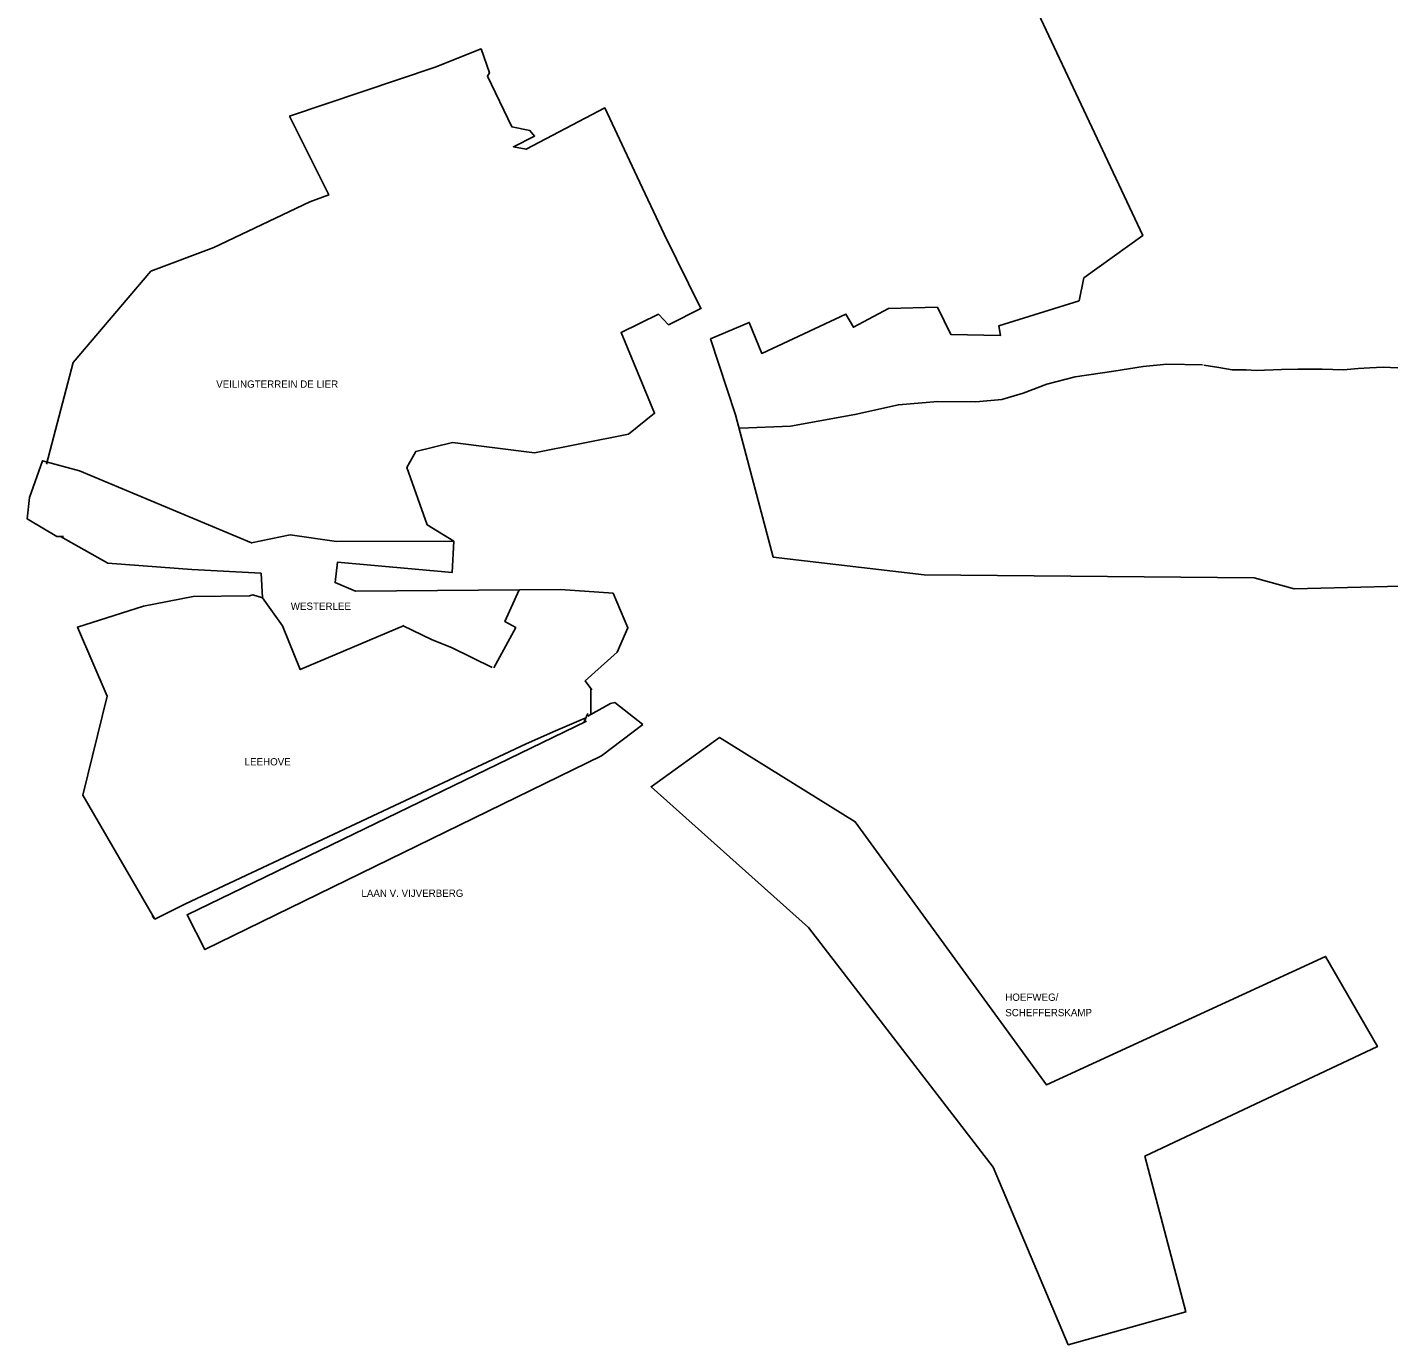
# Model space of a CAD drawing. Extents: x 69068 to 80855, y 440023 to 451362.
# Drawn here: x 74587 to 76267, y 442401 to 444027 of the extents above; entities that cross this region are included whole.
import ezdxf

# ---------------------------------------------------------------- set-up
doc = ezdxf.new("R2010")
doc.units = 0
doc.layers.add('Bemalingsgebiedsgrens', color=7, linetype='Continuous')
doc.layers.add('RIO_Leidingen', color=7, linetype='Continuous')

msp = doc.modelspace()

# ---------------------------------------------------------------- linework, layer by layer
at = {"layer": 'Bemalingsgebiedsgrens'}
for p, q in [((74876, 443353.2), (74790.3, 443357.4)), ((74877.6, 443322.6), (74876, 443353.2)), ((75086.2, 443271.4), (75051.2, 443287.9)), ((75111.7, 443261), (75086.2, 443271.4)), ((75161, 443236.7), (75111.7, 443261)), ((75282.5, 443179.3), (75282.6, 443211)), ((75274.4, 443169.4), (75279.1, 443179.8))]:
    msp.add_line(p, q, dxfattribs=at)
for points in [[(75831.3, 444051), (75963.9, 443769.8), (75890.9, 443717.4), (75885.1, 443689.3), (75785.9, 443658.2), (75788.1, 443646.3), (75726.8, 443647.6), (75710.2, 443681.2), (75650.1, 443679.5), (75606.7, 443656.5), (75597.4, 443672.7), (75493.5, 443624.2), (75478.2, 443662.5), (75430.5, 443642.1), (75461.2, 443548.4), (75507.7, 443372.6), (75694, 443350.9), (76100.9, 443347.5), (76150.3, 443333.9), (76298.4, 443337.3)], [(74611.3, 443487.5), (74644.1, 443612.9), (74740, 443725.6), (74817.6, 443755), (74935.9, 443811.2), (74959.4, 443819.8), (74911, 443917.1), (75090.7, 443977.6), (75147.3, 444000), (75157.6, 443970.5), (75155.1, 443966.5), (75185.1, 443903.9), (75207.5, 443899.2), (75213.3, 443892.5), (75187.2, 443879.3), (75202.8, 443876.1), (75300, 443927.1), (75336.5, 443849.3), (75373, 443771.6), (75418.4, 443679.5), (75416.6, 443679.3)], [(75419.1, 443680), (75378.7, 443659.7), (75366.2, 443672.6), (75320.1, 443650.1), (75361.4, 443550.5), (75329.1, 443524.4), (75213, 443501.6), (75112.2, 443514.2), (75066.7, 443503.3), (75055.7, 443483.3), (75080.6, 443412.8), (75113.6, 443392.5)], [(75466.9, 443531.9), (75529, 443534.4), (75608.5, 443548.7), (75662.2, 443560.9), (75710.7, 443564.8), (75757.5, 443564.3), (75789.6, 443567.3), (75816, 443575.1), (75845.3, 443586.3), (75880.4, 443595.2), (75927.8, 443602.2), (75964.3, 443608), (75993.5, 443610.8), (76037.5, 443610)], [(76038.9, 443609.7), (76057.3, 443606.9), (76074, 443604.1), (76091, 443603.8), (76103.6, 443603.3), (76134.8, 443604.4), (76155.1, 443604.7), (76184.9, 443604.9), (76211.1, 443604.1), (76229.5, 443605.8), (76243.7, 443606.6), (76260.4, 443607.2), (76278.5, 443606.3)], [(74591.2, 443417.7), (74587.4, 443420.1), (74590, 443446.6), (74606.1, 443491.8), (74651.8, 443479.2), (74864.1, 443390.4), (74911.8, 443400.5), (74968.9, 443392.1), (75113.6, 443392.5), (75111.5, 443353.7), (74970.2, 443366.8), (74967.2, 443341.5), (74992.5, 443330.7)], [(74632.1, 443398.3), (74623.8, 443398.5), (74589.3, 443418.9)], [(74790.3, 443357.4), (74686.9, 443365.4), (74628.3, 443398.4)], [(75276.7, 443174.6), (75276.7, 443174.6), (75239.2, 443158.3), (75203.1, 443142.3), (74782.6, 442944.8), (74744.8, 442926.2), (74744.8, 442926.2), (74741.8, 442929.2), (74744.8, 442926.2), (74744.8, 442926.2), (74656.1, 443079.3), (74685.8, 443201.1), (74649.4, 443286.6), (74731, 443312.2), (74791.9, 443324.1), (74861.5, 443325), (74865.7, 443326.5), (74877.6, 443322.6), (74902.2, 443287.9), (74924.1, 443234.1), (75052.5, 443288.6)], [(74992.5, 443330.7), (75245.4, 443332.9), (75310.1, 443328.3), (75328.5, 443285.4), (75315.3, 443255.4)], [(75194.3, 443332.3), (75176.8, 443293.3), (75190.1, 443285.9), (75162.9, 443236.4)], [(75315.3, 443255.4), (75275.8, 443220.2), (75283.8, 443209)], [(75306.8, 443192.2), (75278.9, 443176.7)], [(75347, 443166.5), (75312.5, 443193.4), (75306.8, 443192.4)], [(75277.2, 443170.6), (74784.5, 442931.5), (74806.5, 442888.5), (75295.9, 443127.5), (75347, 443166.5)]]:
    msp.add_lwpolyline(points, dxfattribs=at)
msp.add_lwpolyline([(75441.5, 443150.1), (75357.1, 443089.4), (75551.2, 442915.6), (75779, 442620.2), (75871.8, 442400.9), (76016.9, 442441.4), (75966.3, 442633.7), (76253.2, 442768.8), (76189.1, 442880.1), (75844.8, 442721.5), (75608.9, 443046.2)], close=True, dxfattribs=at)

# ---------------------------------------------------------------- texts
at = {"layer": 'RIO_Leidingen'}
for s, p in [('VEILINGTERREIN DE LIER', (74820.5, 443581.9)), ('WESTERLEE', (74912.5, 443307.8)), ('LEEHOVE', (74855.6, 443115.8)), ('LAAN V. VIJVERBERG', (74999.7, 442953.6)), ('HOEFWEG/', (75794, 442825.3)), ('SCHEFFERSKAMP', (75794, 442806.3))]:
    msp.add_text(s, height=9, dxfattribs=at).set_placement(p)

doc.saveas('drawing.dxf')
